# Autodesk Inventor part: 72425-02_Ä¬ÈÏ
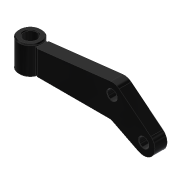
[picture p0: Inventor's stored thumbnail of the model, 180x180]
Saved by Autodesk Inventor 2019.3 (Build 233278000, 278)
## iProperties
Created: 2010-06
Part Number: 72425-02_Ä¬ÈÏ
Material: Ogólny
Document SubType Name: Modeling
Designer: CADENGINEERING4
Density: 1 g/cm^3
Appearance: Gładki — czarny
Author: CADENGINEERING4
Revision Number: ÈÎºÎ
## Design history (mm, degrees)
feature "NONE"
feature "NONE:1"
feature "NONE:2"
feature "NONE:3"
node "Bryła1"
node "Bryła2"
node "Bryła3"
node "Bryła4"
